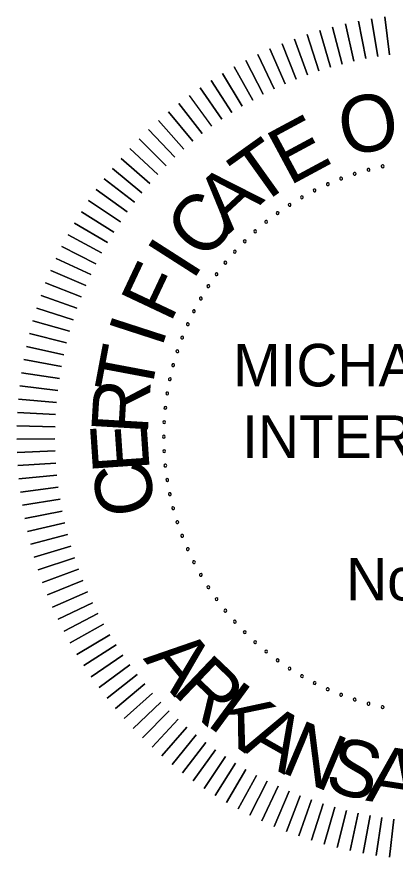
# Model space of a CAD drawing. Extents: x -43543 to 34500, y -13675 to 11152.
# Drawn here: x 6360 to 7473, y -8579 to -6110 of the extents above; entities that cross this region are included whole.
import ezdxf

# ---------------------------------------------------------------- set-up
doc = ezdxf.new("R2010")
doc.units = 0
doc.layers.add('G-ANNO-TEXT', color=7, linetype='Continuous')

msp = doc.modelspace()

# ---------------------------------------------------------------- linework, layer by layer
at = {"layer": 'G-ANNO-TEXT'}
for points in [[(7386.1, -6232.8), (7364.4, -6122.7)], [(7364.4, -6122.7), (7386.1, -6232.8)], [(7421.1, -6226.5), (7402.9, -6115.8)], [(7402.9, -6115.8), (7421.1, -6226.5)], [(7456.2, -6221.3), (7441.6, -6110)], [(7441.6, -6110), (7456.2, -6221.3)], [(7316.7, -6248.7), (7288.2, -6140.2)], [(7288.2, -6140.2), (7316.7, -6248.7)], [(7351.3, -6240.2), (7326.2, -6130.8)], [(7326.2, -6130.8), (7351.3, -6240.2)], [(7248.5, -6268.9), (7213.3, -6162.4)], [(7213.3, -6162.4), (7248.5, -6268.9)], [(7282.5, -6258.3), (7250.6, -6150.7)], [(7250.6, -6150.7), (7282.5, -6258.3)], [(7181.8, -6293.4), (7139.9, -6189.3)], [(7139.9, -6189.3), (7181.8, -6293.4)], [(7215, -6280.7), (7176.4, -6175.3)], [(7176.4, -6175.3), (7215, -6280.7)], [(7116.6, -6322), (7068.3, -6220.7)], [(7068.3, -6220.7), (7116.6, -6322)], [(7149, -6307.2), (7103.8, -6204.5)], [(7103.8, -6204.5), (7149, -6307.2)], [(7084.8, -6337.8), (7033.3, -6238.1)], [(7033.3, -6238.1), (7084.8, -6337.8)], [(7053.5, -6354.7), (6998.8, -6256.6)], [(6998.8, -6256.6), (7053.5, -6354.7)], [(7022.7, -6372.5), (6965, -6276.2)], [(6965, -6276.2), (7022.7, -6372.5)], [(6962.8, -6410.9), (6899.2, -6318.4)], [(6899.2, -6318.4), (6962.8, -6410.9)], [(6992.4, -6391.2), (6931.8, -6296.8)], [(6931.8, -6296.8), (6992.4, -6391.2)], [(6933.8, -6431.5), (6867.4, -6341.1)], [(6905.5, -6453), (6836.2, -6364.7)], [(6836.2, -6364.7), (6905.5, -6453)], [(6877.9, -6475.4), (6805.9, -6389.3)], [(6805.9, -6389.3), (6877.9, -6475.4)], [(6851, -6498.7), (6776.3, -6414.9)], [(6776.3, -6414.9), (6851, -6498.7)], [(6824.8, -6522.8), (6747.5, -6441.4)], [(6747.5, -6441.4), (6824.8, -6522.8)], [(6799.4, -6547.6), (6719.6, -6468.7)], [(6719.6, -6468.7), (6799.4, -6547.6)], [(6774.8, -6573.3), (6692.5, -6497)], [(6692.5, -6497), (6774.8, -6573.3)], [(6751, -6599.8), (6666.4, -6526)], [(6666.4, -6526), (6751, -6599.8)], [(6728, -6626.9), (6641.2, -6555.9)], [(6641.2, -6555.9), (6728, -6626.9)], [(6706, -6654.8), (6616.9, -6586.5)], [(6616.9, -6586.5), (6706, -6654.8)], [(6684.8, -6683.4), (6593.6, -6617.9)], [(6593.6, -6617.9), (6684.8, -6683.4)], [(6664.5, -6712.6), (6571.3, -6650)], [(6571.3, -6650), (6664.5, -6712.6)], [(6645.1, -6742.4), (6550, -6682.8)], [(6550, -6682.8), (6645.1, -6742.4)], [(6626.7, -6772.9), (6529.8, -6716.3)], [(6529.8, -6716.3), (6626.7, -6772.9)], [(6609.2, -6803.9), (6510.6, -6750.3)], [(6510.6, -6750.3), (6609.2, -6803.9)], [(6592.8, -6835.4), (6492.5, -6785)], [(6492.5, -6785), (6592.8, -6835.4)], [(6577.3, -6867.4), (6475.5, -6820.2)], [(6475.5, -6820.2), (6577.3, -6867.4)], [(6562.8, -6899.9), (6459.6, -6855.9)], [(6459.6, -6855.9), (6562.8, -6899.9)], [(6549.4, -6932.8), (6444.8, -6892.1)], [(6444.8, -6892.1), (6549.4, -6932.8)], [(6537, -6966.2), (6431.2, -6928.8)], [(6431.2, -6928.8), (6537, -6966.2)], [(6525.7, -6999.9), (6418.8, -6965.8)], [(6418.8, -6965.8), (6525.7, -6999.9)], [(6515.4, -7033.9), (6407.5, -7003.2)], [(6407.5, -7003.2), (6515.4, -7033.9)], [(6506.2, -7068.3), (6397.4, -7041)], [(6397.4, -7041), (6506.2, -7068.3)], [(6498.1, -7102.9), (6388.5, -7079.1)], [(6388.5, -7079.1), (6498.1, -7102.9)], [(6491.1, -7137.8), (6380.8, -7117.4)], [(6380.8, -7117.4), (6491.1, -7137.8)], [(6485.2, -7172.9), (6374.3, -7155.9)], [(6374.3, -7155.9), (6485.2, -7172.9)], [(6480.4, -7208.1), (6369, -7194.7)], [(6369, -7194.7), (6480.4, -7208.1)], [(6476.7, -7243.5), (6364.9, -7233.5)], [(6364.9, -7233.5), (6476.7, -7243.5)], [(6474.1, -7279), (6362, -7272.5)], [(6362, -7272.5), (6474.1, -7279)], [(6472.6, -7314.5), (6360.4, -7311.6)], [(6360.4, -7311.6), (6472.6, -7314.5)], [(6472.2, -7350.1), (6360, -7350.7)], [(6360, -7350.7), (6472.2, -7350.1)], [(6473, -7385.6), (6360.8, -7389.8)], [(6360.8, -7389.8), (6473, -7385.6)], [(6474.9, -7421.1), (6362.9, -7428.8)], [(6362.9, -7428.8), (6474.9, -7421.1)], [(6477.9, -7456.6), (6366.2, -7467.8)], [(6366.2, -7467.8), (6477.9, -7456.6)], [(6482, -7491.9), (6370.7, -7506.6)], [(6370.7, -7506.6), (6482, -7491.9)], [(6487.2, -7527.1), (6376.4, -7545.3)], [(6376.4, -7545.3), (6487.2, -7527.1)], [(6493.5, -7562.1), (6383.4, -7583.7)], [(6383.4, -7583.7), (6493.5, -7562.1)], [(6500.9, -7596.9), (6391.5, -7622)], [(6391.5, -7622), (6500.9, -7596.9)], [(6509.4, -7631.4), (6400.8, -7659.9)], [(6400.8, -7659.9), (6509.4, -7631.4)], [(6519, -7665.7), (6411.4, -7697.6)], [(6411.4, -7697.6), (6519, -7665.7)], [(6529.6, -7699.6), (6423.1, -7734.9)], [(6423.1, -7734.9), (6529.6, -7699.6)], [(6541.3, -7733.2), (6435.9, -7771.8)], [(6435.9, -7771.8), (6541.3, -7733.2)], [(6554.1, -7766.4), (6450, -7808.3)], [(6450, -7808.3), (6554.1, -7766.4)], [(6567.9, -7799.2), (6465.1, -7844.3)], [(6465.1, -7844.3), (6567.9, -7799.2)], [(6582.7, -7831.5), (6481.4, -7879.9)], [(6481.4, -7879.9), (6582.7, -7831.5)], [(6598.5, -7863.4), (6498.8, -7914.9)], [(6498.8, -7914.9), (6598.5, -7863.4)], [(6615.3, -7894.7), (6517.3, -7949.3)], [(6517.3, -7949.3), (6615.3, -7894.7)], [(6633.1, -7925.5), (6536.8, -7983.2)], [(6536.8, -7983.2), (6633.1, -7925.5)], [(6651.9, -7955.7), (6557.4, -8016.4)], [(6557.4, -8016.4), (6651.9, -7955.7)], [(6671.6, -7985.3), (6579.1, -8048.9)], [(6579.1, -8048.9), (6671.6, -7985.3)], [(6692.2, -8014.3), (6601.7, -8080.8)], [(6601.7, -8080.8), (6692.2, -8014.3)], [(6713.7, -8042.6), (6625.4, -8111.9)], [(6625.4, -8111.9), (6713.7, -8042.6)], [(6736.1, -8070.3), (6650, -8142.3)], [(6650, -8142.3), (6736.1, -8070.3)], [(6759.3, -8097.2), (6675.6, -8171.9)], [(6675.6, -8171.9), (6759.3, -8097.2)], [(6783.4, -8123.4), (6702, -8200.7)], [(6702, -8200.7), (6783.4, -8123.4)], [(6808.3, -8148.8), (6729.4, -8228.6)], [(6729.4, -8228.6), (6808.3, -8148.8)], [(6834, -8173.4), (6757.6, -8255.6)], [(6757.6, -8255.6), (6834, -8173.4)], [(6786.7, -8281.8), (6860.4, -8197.2)], [(6860.4, -8197.2), (6786.7, -8281.8)], [(6816.5, -8307), (6887.6, -8220.1)], [(6887.6, -8220.1), (6816.5, -8307)], [(6847.2, -8331.3), (6915.5, -8242.2)], [(6915.5, -8242.2), (6847.2, -8331.3)], [(6878.6, -8354.6), (6944, -8263.4)], [(6944, -8263.4), (6878.6, -8354.6)], [(6910.7, -8376.9), (6973.3, -8283.7)], [(6973.3, -8283.7), (6910.7, -8376.9)], [(6943.5, -8398.1), (7003.1, -8303.1)], [(7003.1, -8303.1), (6943.5, -8398.1)], [(6976.9, -8418.4), (7033.5, -8321.5)], [(7033.5, -8321.5), (6976.9, -8418.4)], [(7011, -8437.6), (7064.5, -8338.9)], [(7064.5, -8338.9), (7011, -8437.6)], [(7045.6, -8455.7), (7096, -8355.4)], [(7096, -8355.4), (7045.6, -8455.7)], [(7080.8, -8472.7), (7128.1, -8370.9)], [(7128.1, -8370.9), (7080.8, -8472.7)], [(7116.6, -8488.6), (7160.6, -8385.3)], [(7160.6, -8385.3), (7116.6, -8488.6)], [(7152.8, -8503.3), (7193.5, -8398.7)], [(7193.5, -8398.7), (7152.8, -8503.3)], [(7189.4, -8516.9), (7226.8, -8411.1)], [(7226.8, -8411.1), (7189.4, -8516.9)], [(7226.5, -8529.4), (7260.5, -8422.5)], [(7260.5, -8422.5), (7226.5, -8529.4)], [(7263.9, -8540.7), (7294.6, -8432.7)], [(7294.6, -8432.7), (7263.9, -8540.7)], [(7301.7, -8550.8), (7329, -8441.9)], [(7329, -8441.9), (7301.7, -8550.8)], [(7339.7, -8559.7), (7363.6, -8450)], [(7363.6, -8450), (7339.7, -8559.7)], [(7378, -8567.4), (7398.5, -8457)], [(7398.5, -8457), (7378, -8567.4)], [(7416.6, -8573.9), (7433.5, -8463)], [(7433.5, -8463), (7416.6, -8573.9)], [(7455.3, -8579.2), (7468.8, -8467.8)], [(7468.8, -8467.8), (7455.3, -8579.2)]]:
    msp.add_lwpolyline(points, dxfattribs=at)
for centre, start, end in [((7353.4, -6571.4), 18, 198), ((7394.2, -6559.3), 15, 195), ((7394.2, -6559.3), 195, 15), ((7435.6, -6549.3), 12, 192), ((7435.6, -6549.3), 192, 12), ((7313.4, -6585.5), 21, 201), ((7313.4, -6585.5), 201, 21), ((7353.4, -6571.4), 198, 18), ((7235.7, -6620.1), 27, 207), ((7274.1, -6601.8), 24, 204), ((7274.1, -6601.8), 204, 24), ((7198.3, -6640.4), 30, 210), ((7198.3, -6640.4), 210, 30), ((7235.7, -6620.1), 207, 27), ((7162.1, -6662.6), 33, 213), ((7162.1, -6662.6), 213, 33), ((7127, -6686.7), 36, 216), ((7127, -6686.7), 216, 36), ((7093.3, -6712.6), 39, 219), ((7093.3, -6712.6), 219, 39), ((7061, -6740.2), 42, 222), ((7061, -6740.2), 222, 42), ((7030.1, -6769.5), 45, 225), ((7030.1, -6769.5), 225, 45), ((7000.9, -6800.3), 48, 228), ((7000.9, -6800.3), 228, 48), ((6973.3, -6832.6), 51, 231), ((6973.3, -6832.6), 231, 51), ((6947.4, -6866.4), 54, 234), ((6947.4, -6866.4), 234, 54), ((6923.3, -6901.4), 57, 237), ((6923.3, -6901.4), 237, 57), ((6901.1, -6937.7), 60, 240), ((6901.1, -6937.7), 240, 60), ((6880.8, -6975), 63, 243), ((6880.8, -6975), 243, 63), ((6862.5, -7013.4), 66, 246), ((6862.5, -7013.4), 246, 66), ((6846.2, -7052.7), 69, 249), ((6846.2, -7052.7), 249, 69), ((6832, -7092.8), 72, 252), ((6832, -7092.8), 252, 72), ((6819.9, -7133.6), 75, 255), ((6819.9, -7133.6), 255, 75), ((6810, -7174.9), 78, 258), ((6810, -7174.9), 258, 78), ((6802.3, -7216.7), 81, 261), ((6802.3, -7216.7), 261, 81), ((6796.7, -7258.9), 84, 264), ((6796.7, -7258.9), 264, 84), ((6793.4, -7301.2), 87, 267), ((6793.4, -7301.2), 267, 87), ((6792.3, -7343.7), 90, 270), ((6792.3, -7343.7), 270, 90), ((6793.4, -7386.3), 93, 273), ((6793.4, -7386.3), 273, 93), ((6796.7, -7428.6), 96, 276), ((6796.7, -7428.6), 276, 96), ((6802.3, -7470.8), 99, 279), ((6802.3, -7470.8), 279, 99), ((6810, -7512.6), 102, 282), ((6810, -7512.6), 282, 102), ((6819.9, -7553.9), 105, 285), ((6819.9, -7553.9), 285, 105), ((6832, -7594.7), 108, 288), ((6832, -7594.7), 288, 108), ((6846.2, -7634.8), 111, 291), ((6846.2, -7634.8), 291, 111), ((6862.5, -7674.1), 114, 294), ((6862.5, -7674.1), 294, 114), ((6880.8, -7712.5), 117, 297), ((6880.8, -7712.5), 297, 117), ((6901.1, -7749.8), 120, 300), ((6901.1, -7749.8), 300, 120), ((6923.3, -7786.1), 123, 303), ((6923.3, -7786.1), 303, 123), ((6947.4, -7821.1), 126, 306), ((6947.4, -7821.1), 306, 126), ((6973.3, -7854.9), 129, 309), ((6973.3, -7854.9), 309, 129), ((7000.9, -7887.2), 132, 312), ((7000.9, -7887.2), 312, 132), ((7030.1, -7918), 135, 315), ((7030.1, -7918), 315, 135), ((7061, -7947.3), 138, 318), ((7061, -7947.3), 318, 138), ((7093.3, -7974.9), 141, 321), ((7093.3, -7974.9), 321, 141), ((7127, -8000.8), 144, 324), ((7127, -8000.8), 324, 144), ((7162.1, -8024.9), 147, 327), ((7162.1, -8024.9), 327, 147), ((7198.3, -8047.1), 150, 330), ((7198.3, -8047.1), 330, 150), ((7235.7, -8067.4), 153, 333), ((7235.7, -8067.4), 333, 153), ((7274.1, -8085.7), 156, 336), ((7274.1, -8085.7), 336, 156), ((7313.4, -8102), 339, 159), ((7313.4, -8102), 159, 339), ((7353.4, -8116.1), 162, 342), ((7353.4, -8116.1), 342, 162), ((7394.2, -8128.2), 165, 345), ((7394.2, -8128.2), 345, 165), ((7435.6, -8138.2), 168, 348), ((7435.6, -8138.2), 348, 168)]:
    msp.add_arc(centre, 4.17, start, end, dxfattribs=at)

# ---------------------------------------------------------------- texts
for s, rotation, p in [('O', 10.7295, (7322.8, -6520.5)), ('E', 28.279, (7161, -6607.8)), ('T', 35.5725, (7067.9, -6672.3)), ('A', 42.8659, (6983.3, -6749.4)), ('C', 50.1594, (6913.2, -6832.7)), ('I', 57.4529, (6877, -6888.4)), ('F', 64.7464, (6811.5, -7013)), ('I', 72.0398, (6785.7, -7086.3)), ('T', 79.3333, (6752.6, -7229.9)), ('R', 86.6268, (6744.9, -7340.1)), ('E', 93.9203, (6751.1, -7444.2)), ('C', 101.2137, (6772.4, -7560.1)), ('A', 309.5859, (6729.8, -7996.4)), ('R', 316.3356, (6812.5, -8094.7)), ('K', 323.6428, (6914.5, -8189.3)), ('A', 330.3925, (7018.6, -8264.5)), ('N', 337.1422, (7130.9, -8327)), ('S', 344.4494, (7259.8, -8379.2)), ('A', 351.1991, (7383.9, -8412.6))]:
    msp.add_text(s, height=166.7, rotation=rotation, dxfattribs=at).set_placement(p)
for s, height, p in [('MICHAEL BAKER', 125.016, (6996.1, -7196)), (' INTERNATIONAL', 125.016, (6976, -7406.2)), (' No. 1126', 125.02, (7281.8, -7824.8))]:
    msp.add_text(s, height=height, dxfattribs=at).set_placement(p)

doc.saveas('drawing.dxf')
